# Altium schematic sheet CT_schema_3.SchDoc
size 322 x 302 mm
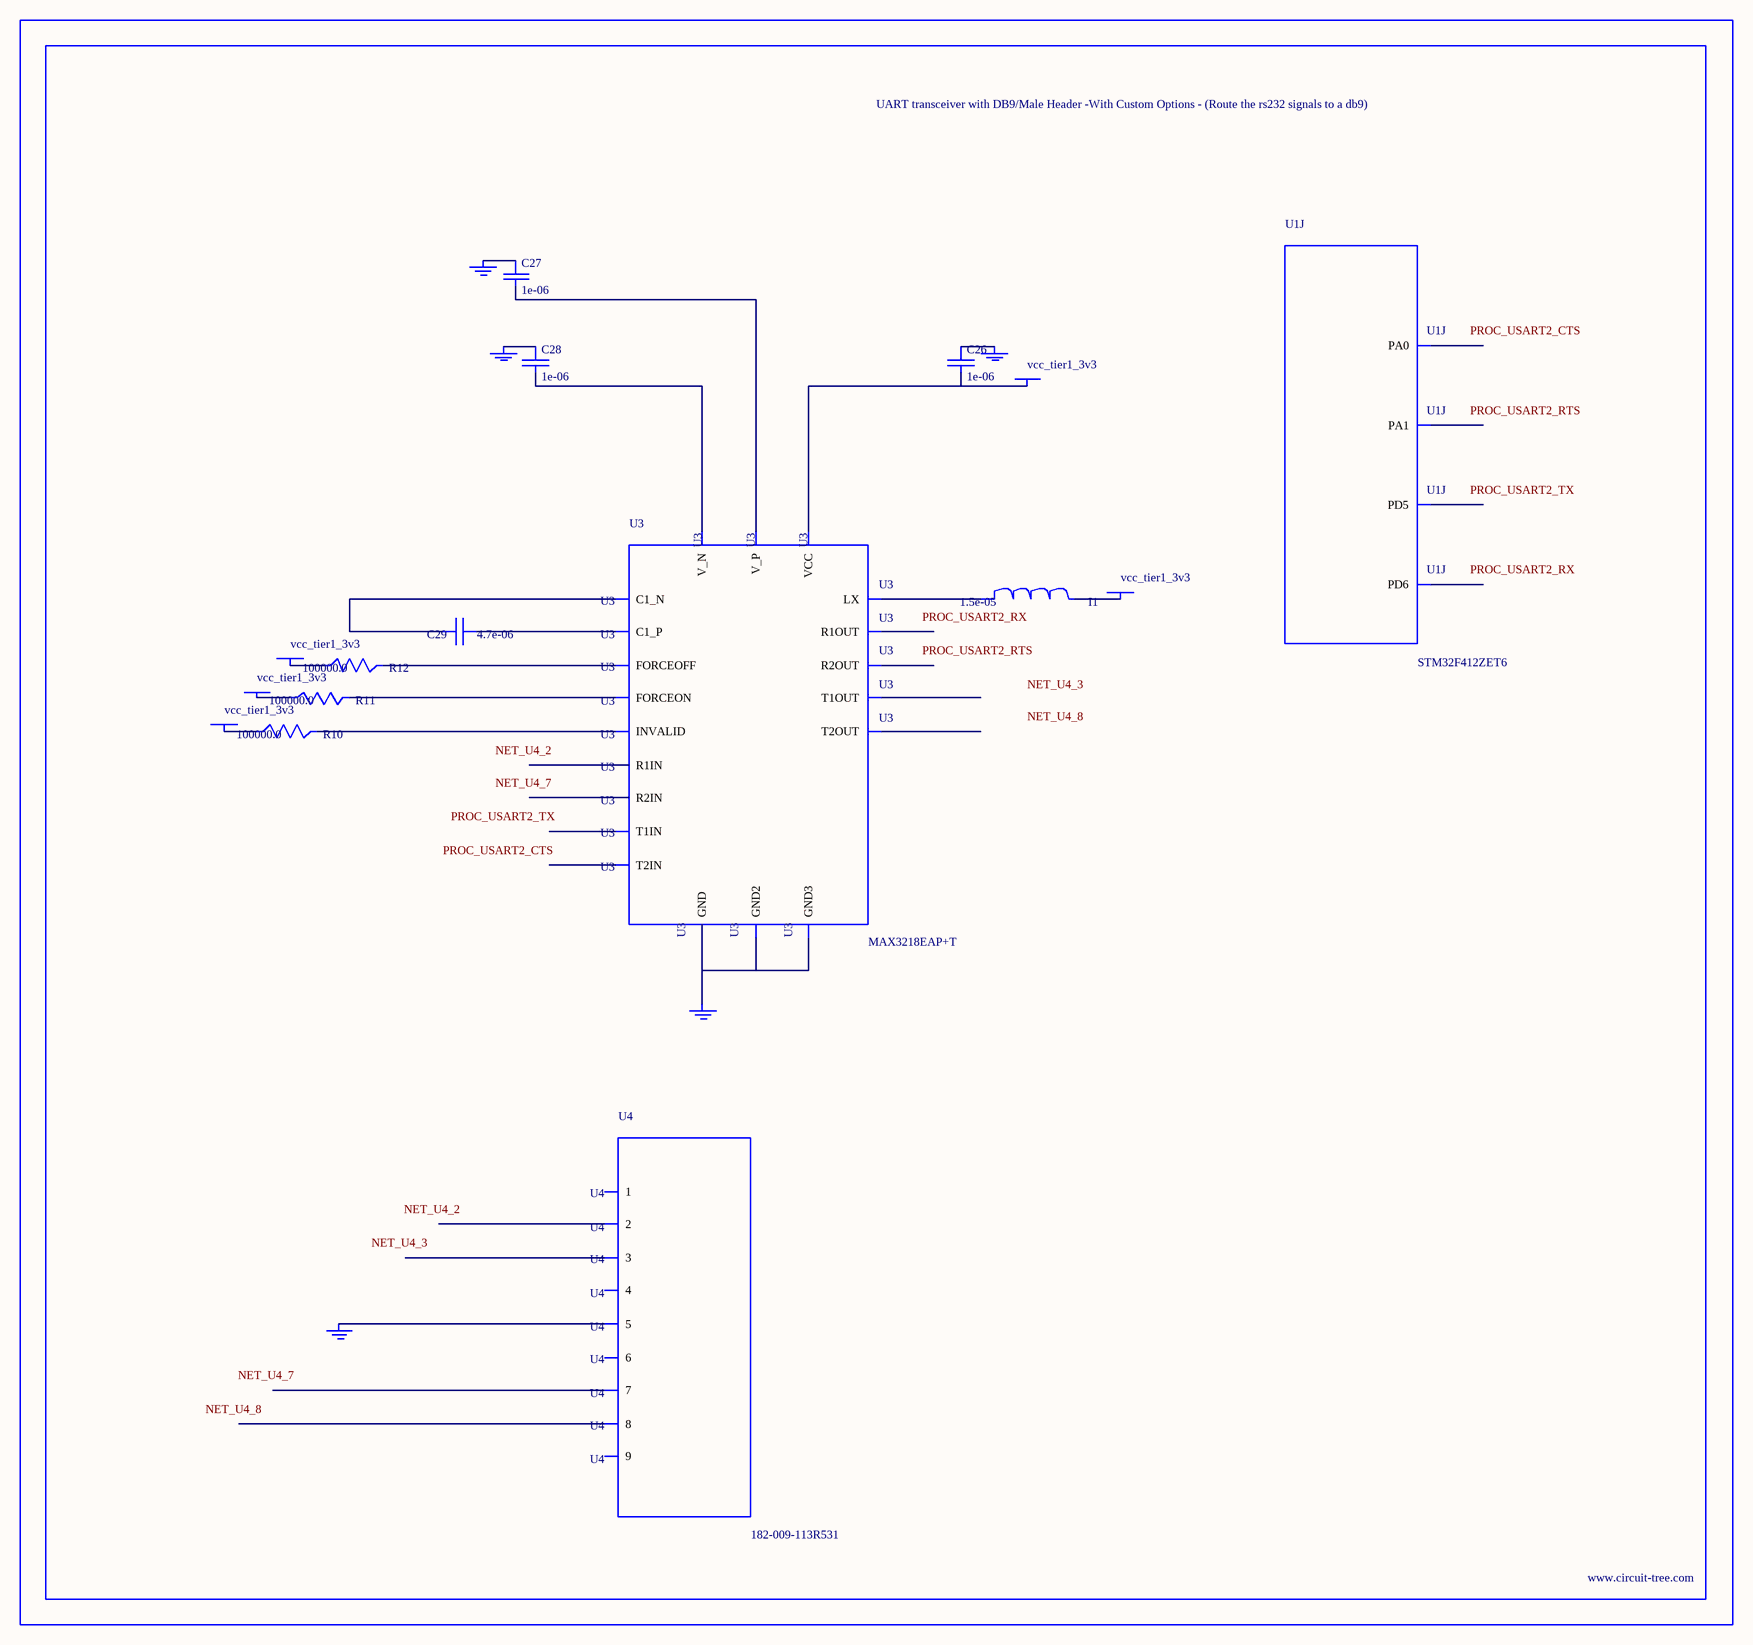
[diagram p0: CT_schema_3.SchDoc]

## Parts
BORDER2  (no value)
C26  1e-06  [C0603]
C27  1e-06  [C0603]
C28  1e-06  [C0603]
C29  4.7e-06  [C0805]
GND_INSTANCE_2_0  (no value)
GND_INSTANCE_2_1  (no value)
GND_INSTANCE_2_2  (no value)
GND_INSTANCE_2_3  (no value)
GND_INSTANCE_2_4  (no value)
I1  1.5e-05  [L1210]
POWER_INSTANCE_2_0  vcc_tier1_3v3
POWER_INSTANCE_2_1  vcc_tier1_3v3
POWER_INSTANCE_2_2  vcc_tier1_3v3
POWER_INSTANCE_2_3  vcc_tier1_3v3
POWER_INSTANCE_2_4  vcc_tier1_3v3
R10  100000.0  [R0603]
R11  100000.0  [R0603]
R12  100000.0  [R0603]
U1  STM32F412ZET6  [LQFP144]  (part J of 13)
U3  MAX3218EAP+T  [SSOP-20]
U4  182-009-113R531  [182-009-MALE]

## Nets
NetC26_1: C26.1 GND_INSTANCE_2_0.0(GND)
NetC26_2: C26.2 POWER_INSTANCE_2_4.0(PWR) U3.6(VCC)
NetC27_1: C27.1 GND_INSTANCE_2_2.0(GND)
NetC27_2: C27.2 U3.19(V_P)
NetC28_1: C28.1 GND_INSTANCE_2_1.0(GND)
NetC28_2: C28.2 U3.15(V_N)
NetC29_1: C29.1 U3.18(C1_P)
NetC29_2: C29.2 U3.16(C1_N)
NetGND_INSTANCE_2_3_0: GND_INSTANCE_2_3.0(GND) U3.5(GND) U3.17(GND2) U3.20(GND3)
NetGND_INSTANCE_2_4_0: GND_INSTANCE_2_4.0(GND) U4.5
NetI1_1: I1.1 U3.1(LX)
NetI1_2: I1.2 POWER_INSTANCE_2_0.0(PWR)
NetPOWER_INSTANCE_2_1_0: POWER_INSTANCE_2_1.0(PWR) R10.1
NetPOWER_INSTANCE_2_2_0: POWER_INSTANCE_2_2.0(PWR) R11.1
NetPOWER_INSTANCE_2_3_0: POWER_INSTANCE_2_3.0(PWR) R12.1
NetR10_2: R10.2 U3.2(INVALID)
NetR11_2: R11.2 U3.3(FORCEON)
NetR12_2: R12.2 U3.4(FORCEOFF)

Not connected (* = marked no-connect by the designer): U1 34(PA0) 35(PA1) 119(PD5) 122(PD6); U3 7(T1IN) 8(T2IN) 9(R1OUT) 10(R2OUT) 11(R2IN) 12(R1IN) 13(T2OUT) 14(T1OUT); U4 1 2 3 4 6 7 8 9

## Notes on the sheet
- Labels drawn without touching a wire or pin: NET_U4_2, NET_U4_3, NET_U4_7, NET_U4_8, PROC_USART2_CTS, PROC_USART2_RTS, PROC_USART2_RX, PROC_USART2_TX

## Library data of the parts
BORDER2 = BORDER_PAGE2
C26-C28 = C0603C105K3RACTU
C29 = C0805C475K4RACTU
GND_INSTANCE_2_0-GND_INSTANCE_2_4 = GND
I1 = L1210R150MDWIT
POWER_INSTANCE_2_0-POWER_INSTANCE_2_4 = PWR
R10-R12 = RC0603JR-07100KL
